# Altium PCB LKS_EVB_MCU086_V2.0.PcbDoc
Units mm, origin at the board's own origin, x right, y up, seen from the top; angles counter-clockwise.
Board outline 66.67 x 39.62 mm, 2 copper layers (Top Layer, Bottom Layer); 45 components, 69 nets, 205 pads, 49 vias.
Unrouted connection lines stored in the file: 4.
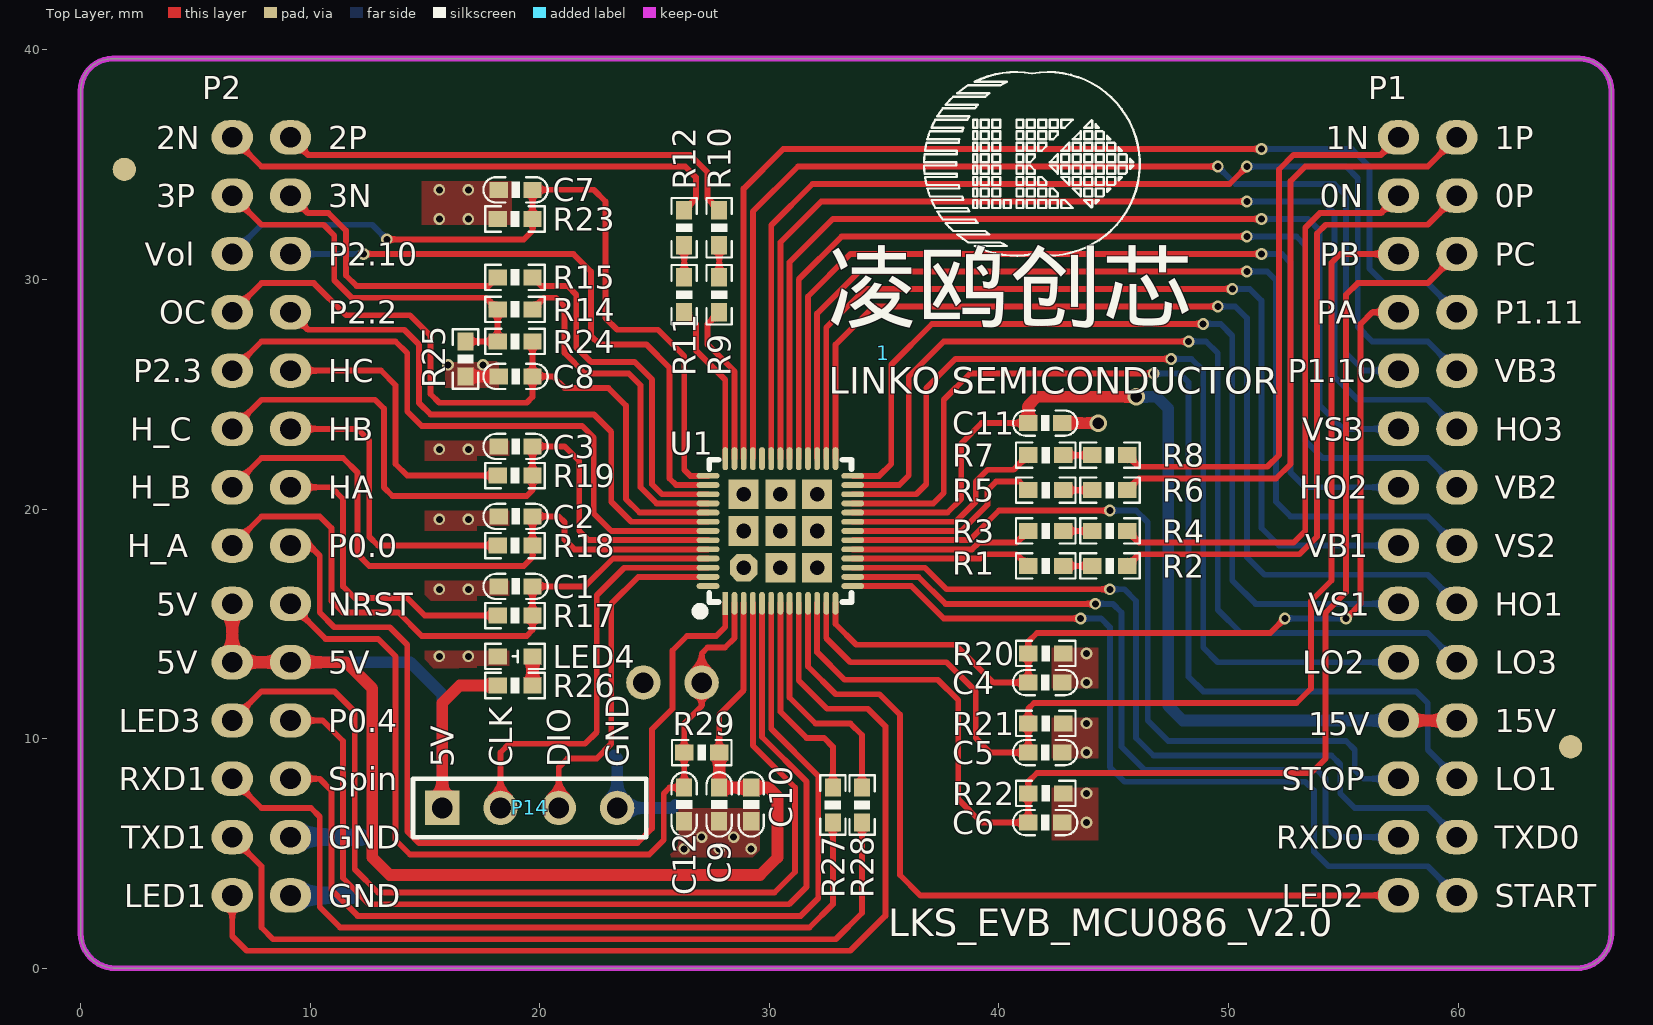
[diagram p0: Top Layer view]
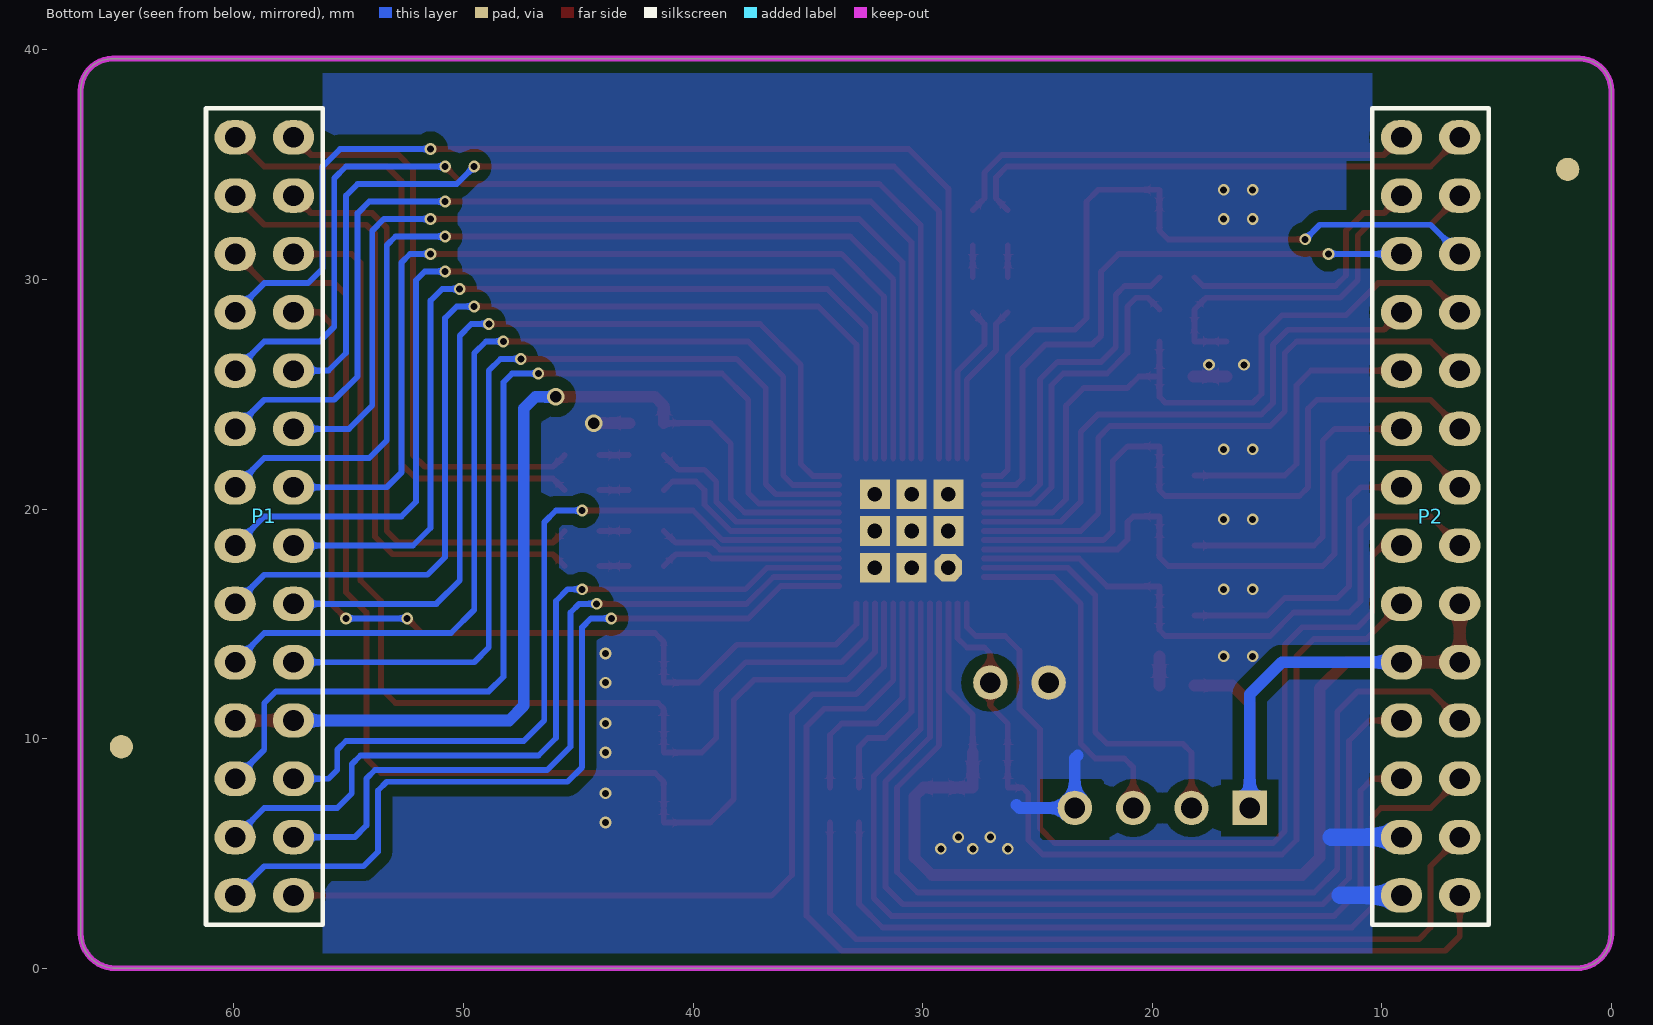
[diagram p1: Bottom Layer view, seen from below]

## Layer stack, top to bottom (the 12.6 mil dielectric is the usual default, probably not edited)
Top Solder: solder mask 0.0102, Solder Resist, Dk 3.5
Top Layer: signal copper 0.0356
Dielectric1: dielectric 0.32, FR-4, Dk 4.8
Bottom Layer: signal copper 0.0356
Bottom Solder: solder mask 0.0102, Solder Resist, Dk 3.5

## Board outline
0,1.524 0,38.227 cw(c1.397,38.227) 1.397,39.624 65.278,39.624 cw(c65.278,38.227) 66.675,38.227 66.675,1.524 cw(c65.151,1.524) 65.151,0 1.524,0 cw(c1.524,1.524)

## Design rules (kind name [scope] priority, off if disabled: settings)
Clearance Clearance_1 [InPolygon] p1: gap=0.508 ignorepadtopadclearanceinfootprint=FALSE except(0: Arc-Hole Track-Hole SMDPad-Hole THPad-Hole Via-Hole Fill-Hole Poly-Hole Region-Hole Text-Hole)
Clearance [All] p2: gap=0.076 ignorepadtopadclearanceinfootprint=FALSE except(0: Arc-Hole Track-Hole SMDPad-Hole THPad-Hole Via-Hole Fill-Hole Poly-Hole Region-Hole Text-Hole)
ComponentClearance [All] p1: gap=0 collisioncheckmode=3 verticalgap=0 showdistances=FALSE
FabricationTestpoint [(IsPad And (OnTopLayer Or OnBottomLayer))] p1: side=3 testpointundercomponent=TRUE minsize=1.016 maxsize=2.54 preferedsize=1.524 minholesize=0 maxholesize=1.016 preferedholesize=0.813 testpointgrid=0.025 allowsidetop=TRUE allowsidebottom=TRUE usegrid=TRUE gridtolerance=0
PolygonConnect [All] p1: connectstyle=Direct reliefconductorwidth=0.635 reliefentries=4 polygonreliefangle="90 Angle" airgapwidth=0.254
RoutingVias [All] p1: holewidth=0.711 width=1.27 viastyle="Through Hole" minholewidth=0 minwidth=0.254 maxholewidth=0.508 maxwidth=2.54
SilkToSolderMaskClearance SilkscreenOverComponentPads [IsPad] p1: minsilkscreentomaskgap=0.254 clearancetoexposedcopper=TRUE
SolderMaskExpansion [All] p1: expansion=0.102 istentingtop=FALSE
Width [All] p1: maxlimit=2.54 minlimit=0.051 preferedwidth=0.254
27 further rules are at their usual default settings.

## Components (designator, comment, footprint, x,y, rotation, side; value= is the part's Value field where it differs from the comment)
1 "LKS_sign" LKS_LOGO2 34.95,26.797 r0 top
C1 "10nF/16V" 0603C 18.948,16.637 r180 top
C2 "10nF/16V" 0603C 18.948,19.685 r180 top
C3 "10nF/16V" 0603C 18.948,22.733 r180 top
C4 "1nF/50V" 0603C 42.012,12.446 r0 top
C5 "1nF/50V" 0603C 42.012,9.398 r0 top
C6 "1nF/50V" 0603C 42.012,6.35 r0 top
C7 "100nF/50V" 0603C 18.947,33.909 r0 top
C8 "1nF/50V" 0603C 18.947,25.781 r0 top
C9 "10uF/16V" 0603C 27.813,7.136 r90 top
C10 "100nF/50V" 0603C 29.21,7.136 r90 top
C11 "4.7uF/35V" 0603C 42.013,23.749 r180 top
C12 "100nF/50V" 0603C 26.289,7.137 r270 top
LED4 "LED" "LED 0603R" 18.923,13.589 r0 top
P1 "Header 14X2A" "HDR 2X14 底层" 57.404,36.195 r180 bottom locked
P2 "Header 14X2A" "HDR 2X14 底层" 6.604,36.195 r180 bottom locked
P14 "Header 4" "HDR 1X4" 15.748,6.985 r0 top
R1 "20K1%" 0603R 42.037,17.526 r180 top value=K
R2 "20K1%" 0603R 44.831,17.526 r180 top value=K
R3 "20K1%" 0603R 42.037,19.05 r180 top value=K
R4 "20K1%" 0603R 44.831,19.05 r180 top value=K
R5 "20K1%" 0603R 42.037,20.828 r180 top value=K
R6 "20K1%" 0603R 44.831,20.828 r180 top value=K
R7 "20K1%" 0603R 42.037,22.352 r180 top value=K
R8 "20K1%" 0603R 44.831,22.352 r180 top value=K
R9 "20K1%" 0603R 27.813,29.337 r270 top value=K
R10 "20K1%" 0603R 27.813,32.258 r270 top value=K
R11 "20K1%" 0603R 26.289,29.337 r270 top value=K
R12 "20K1%" 0603R 26.289,32.258 r270 top value=K
R14 "1K1%" 0603R 18.923,28.702 r0 top value=K
R15 "1K1%" 0603R 18.923,30.099 r0 top value=K
R17 "2K" 0603R 18.923,15.367 r0 top value=K
R18 "2K" 0603R 18.923,18.415 r0 top value=K
R19 "2K" 0603R 18.923,21.463 r0 top value=K
R20 "1K" 0603R 42.037,13.716 r0 top value=K
R21 "1K" 0603R 42.037,10.668 r0 top value=K
R22 "1K" 0603R 42.037,7.62 r0 top value=K
R23 "1K1%" 0603R 18.923,32.639 r0 top value=K
R24 "1K1%" 0603R 18.923,27.305 r180 top value=K
R25 "10R" 0603R 16.764,26.543 r270 top value=10
R26 "330R" 0603R 18.923,12.319 r0 top value=330
R27 "10R" 0603R 32.766,7.112 r270 top
R28 "10R" 0603R 34.036,7.112 r90 top value=100R
R29 "20K" 0603R 27.051,9.398 r180 top value=K
U1 "LKS086" QFN52 30.48,19.05 r90 top locked

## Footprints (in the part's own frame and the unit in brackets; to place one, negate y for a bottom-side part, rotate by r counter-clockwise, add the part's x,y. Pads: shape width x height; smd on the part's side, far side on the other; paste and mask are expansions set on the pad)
0603C [mm] "电容"
  rect 0.8x0.7 smd: 1(-0.737,0) 2(0.738,0)
  silkscreen extent -1.4,-0.55 1.4,0.55, body extent -0.8,-0.41 0.8,0.41, height 0.81
0603R [mm] "电阻"
  rect 0.8x0.7 smd: 1(-0.762,0) 2(0.762,0)
  silkscreen extent -1.3,-0.55 1.3,0.55, body extent -0.8,-0.4 0.8,0.4, height 0.45
"HDR 1X4" [mm] "单排针 2.54mm"
  rect 1.5x1.5 hole 0.9: 1(0,0)
  round 1.5 hole 0.9: 2(2.54,0) 3(5.08,0) 4(7.62,0)
  silkscreen extent -1.27,-1.27 8.89,1.27, body extent -1.27,-1.27 8.89,1.27, height 8.5
"HDR 2X14 底层" [mm] "双排针 2.54mm 底层"
  oval 1.8x1.5 hole 0.9: 1(0,0) 2(0,-2.54) 3(0,-5.08) 4(0,-7.62) 5(0,-10.16) 6(0,-12.7) 7(0,-15.24) 8(0,-17.78) 9(0,-20.32) 10(0,-22.86) 11(0,-25.4) 12(0,-27.94) 13(0,-30.48) 14(0,-33.02) 15(-2.54,0) 16(-2.54,-2.54) 17(-2.54,-5.08) 18(-2.54,-7.62) 19(-2.54,-10.16) 20(-2.54,-12.7) 21(-2.54,-15.24) 22(-2.54,-17.78) 23(-2.54,-20.32) 24(-2.54,-22.86) 25(-2.54,-25.4) 26(-2.54,-27.94) 27(-2.54,-30.48) 28(-2.54,-33.02)
  silkscreen extent -3.81,-34.29 1.27,1.27, body extent -3.81,-34.29 1.27,1.27, height 8.5
"LED 0603R" [mm] "LED"
  rect 0.8x0.7 smd: 1(0.762,0) 2(-0.762,0)
  silkscreen extent -1.3,-0.55 1.3,0.55, body extent -0.8,-0.4 0.8,0.4, height 0.47
LKS_LOGO2 [mm] "标?"
  silkscreen extent 1.79,4.24 11.18,12.24
QFN52 [mm] "LINKO-086"
  oct 1.2x1.2 hole 0.635: 0(-1.6,1.6)
  rect 1.3x1.3 hole 0.635: 0(-1.6,0) 0(-1.6,-1.6) 0(0,1.6) 0(0,0) 0(0,-1.6) 0(1.6,1.6) 0(1.6,0) 0(1.6,-1.6)
  rect 1x0.25 smd: 1(-3.15,2.4)
  oval 1x0.25 smd: 2(-3.15,2) 3(-3.15,1.6) 4(-3.15,1.2) 5(-3.15,0.8) 6(-3.15,0.4) 7(-3.15,0) 8(-3.15,-0.4) 9(-3.15,-0.8) 10(-3.15,-1.2) 11(-3.15,-1.6) 12(-3.15,-2) 13(-3.15,-2.4) 27(3.15,-2.4) 28(3.15,-2) 29(3.15,-1.6) 30(3.15,-1.2) 31(3.15,-0.8) 32(3.15,-0.4) 33(3.15,0) 34(3.15,0.4) 35(3.15,0.8) 36(3.15,1.2) 37(3.15,1.6) 38(3.15,2) 39(3.15,2.4)
  oval 0.25x1 smd: 14(-2.4,-3.15) 15(-2,-3.15) 16(-1.6,-3.15) 17(-1.2,-3.15) 18(-0.8,-3.15) 19(-0.4,-3.15) 20(0,-3.15) 21(0.4,-3.15) 22(0.8,-3.15) 23(1.2,-3.15) 24(1.6,-3.15) 25(2,-3.15) 26(2.4,-3.15) 40(2.4,3.15) 41(2,3.15) 42(1.6,3.15) 43(1.2,3.15) 44(0.8,3.15) 45(0.4,3.15) 46(0,3.15) 47(-0.4,3.15) 48(-0.8,3.15) 49(-1.2,3.15) 50(-1.6,3.15) 51(-2,3.15) 52(-2.4,3.15)
  silkscreen extent -3.61,-3.1 3.1,3.61, body extent -3,-3 3,3, height 0.9

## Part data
C1 C2 C3 C4 C5 C6: library part CAP, "Capacitor"
C7 C8 C9 C10 C11 C12: library part C, "Capacitor"
LED4: "LED_Light"
P1 P2: "Header, 14-Pin, Dual row"
P14: "Header, 4-Pin"
R1 R2 R3 R4 R5 R6 R7 R8 R9 R10 R11 R12 R14 R15 R17 R18 R19 R20 R21 R22 R23 R24 R25 R26 R29: library part Res, "Resistor"
R27 R28: library part Res2, "Resistor"
U1: library part LKS086N8Q8, "芯片"

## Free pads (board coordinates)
  round 1.5 hole 0.9: 0(27.051,12.446) 1(24.511,12.446)
  round 1.016 all layers, no hole: 1(1.905,34.798) 2(64.897,9.652)

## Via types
v1: diameter 0.508, hole 0.305, Top Layer to Bottom Layer, 47 vias
v2: diameter 0.762, hole 0.508, Top Layer to Bottom Layer, 2 vias

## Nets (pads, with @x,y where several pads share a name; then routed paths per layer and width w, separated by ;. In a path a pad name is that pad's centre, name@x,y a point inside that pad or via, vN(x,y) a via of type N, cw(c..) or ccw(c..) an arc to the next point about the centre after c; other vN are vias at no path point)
+5V: C9.2 C10.2 P2.9 P2.10 P2.24 P14.1 R26.1 R29.1 U1.3 | length 68
  Top Layer w0.254: R29.1 27.813,11.049 28.88,12.116 U1.3
  Top Layer w0.508: P2.9 P2.10 P2.24 11.557,13.335 12.7,12.192 12.7,4.826 13.462,4.064 29.591,4.064 30.353,4.826 30.353,7.493 29.972,7.874 C10.2 C9.2 R29.1 ; P14.1 15.748,11.557 16.51,12.319 R26.1
  Bottom Layer w0.508: P2.24 14.351,13.335 15.748,11.938 P14.1
+15V: C11.2 P1.11 P1.25 U1.22 | length 43.7
  Top Layer w0.254: U1.22 37.757,19.85 38.354,20.447 38.354,22.86 39.243,23.749 C11.2
  Top Layer w0.508: C11.2 41.275,24.511 41.656,24.892 v2(45.974,24.892) ; P1.11 P1.25
  Bottom Layer w0.508: v2(45.974,24.892) 46.863,24.892 47.371,24.384 47.371,11.43 48.006,10.795 P1.11
GND: C1.2 C2.2 C3.2 C4.2 C5.2 C6.2 C7.1 C8.1 C9.1 C10.1 C11.1 C12.2 LED4.2 P2.16 P2.27 P2.28 P14.4 pad.1@24.511,12.446 R15.1 R20.2 R21.2 R22.2 R23.1 R25.2 U1.0 | length 25.6
  Top Layer w0.254: P2.16 9.906,32.893 10.795,32.893 11.557,32.131 11.557,30.182 12.021,29.718 17.78,29.718 R15.1
  Top Layer w0.508: R25.2 C8.1 ; C11.1 v2(44.323,23.749)
  Bottom Layer w0.508: 23.241,9.271 23.368,9.144 P14.4 25.781,6.985 25.908,7.112
  Bottom Layer w0.762: P2.28 11.811,3.175 ; P2.27 12.192,5.715
  other v1: 26.289,5.207 27.813,5.207 29.21,5.207 27.051,5.715 28.448,5.715 43.815,6.35 43.815,7.62 43.815,9.398 43.815,10.668 43.815,12.446 15.621,13.589 16.891,13.589 43.815,13.716 15.621,16.51 16.891,16.51 15.621,19.558 16.891,19.558 15.621,22.606 16.891,22.606 16.002,26.289 17.526,26.289 15.621,32.639 16.891,32.639 15.621,33.909 16.891,33.909
HALL_U: C1.1 P2.8 R17.2 U1.49 | length 27.8
  Top Layer w0.254: P2.8 7.874,19.685 10.414,19.685 10.922,19.177 10.922,16.002 11.43,15.494 13.843,15.494 14.859,14.478 19.431,14.478 19.685,14.732 R17.2 C1.1 21.971,16.637 23.184,17.85 U1.49
HALL_V: C2.1 P2.7 R18.2 U1.48 | length 28.3
  Top Layer w0.254: P2.7 7.874,22.225 11.43,22.225 12.065,21.59 12.065,18.034 12.573,17.526 19.304,17.526 19.685,17.907 R18.2 C2.1 20.828,19.685 21.082,19.431 21.082,18.669 21.501,18.25 U1.48
HALL_W: C3.1 P2.6 R19.2 U1.47 | length 30.5
  Top Layer w0.254: P2.6 7.874,24.765 12.827,24.765 13.208,24.384 13.208,20.955 13.589,20.574 19.431,20.574 19.685,20.828 R19.2 C3.1 21.082,22.733 21.717,22.098 21.717,19.05 22.117,18.65 U1.47
HO1: P1.23 U1.27 | length 44.2
  Top Layer w0.254: U1.27 32.88,27.165 34.544,28.829 v1(49.53,28.829)
  Bottom Layer w0.254: v1(49.53,28.829) 50.292,28.829 50.8,28.321 50.8,17.907 51.562,17.145 58.674,17.145 P1.23
HO2: P1.7 U1.30 | length 43.1
  Top Layer w0.254: U1.30 31.68,29.267 33.528,31.115 v1(51.435,31.115)
  Bottom Layer w0.254: v1(51.435,31.115) 52.324,31.115 52.705,30.734 52.705,21.59 53.34,20.955 P1.7
HO3: P1.20 U1.33 | length 47.9
  Top Layer w0.254: U1.33 30.48,31.623 32.258,33.401 v1(50.8,33.401)
  Bottom Layer w0.254: v1(50.8,33.401) 54.102,33.401 54.61,32.893 54.61,25.781 55.626,24.765 58.674,24.765 P1.20
HU: P2.21 R17.1 | length 13.6
  Top Layer w0.254: P2.21 10.922,20.955 11.43,20.447 11.43,16.637 11.938,16.129 14.224,16.129 14.986,15.367 R17.1
HV: P2.20 R18.1 | length 13.6
  Top Layer w0.254: P2.20 12.065,23.495 12.573,22.987 12.573,18.796 12.954,18.415 R18.1
HW: P2.19 R19.1 | length 12.9
  Top Layer w0.254: P2.19 13.081,26.035 13.716,25.4 13.716,21.971 14.224,21.463 R19.1
LED1: P2.14 U1.9 | length 47.3
  Top Layer w0.254: P2.14 6.604,1.397 7.239,0.762 33.528,0.762 35.052,2.286 35.052,10.541 34.29,11.303 32.512,11.303 31.28,12.535 U1.9
LED2: P1.14 U1.10 | length 36.7
  Top Layer w0.254: U1.10 31.68,13.151 32.893,11.938 34.798,11.938 35.687,11.049 35.687,4.064 36.576,3.175 P1.14
LED3: P2.11 U1.4 | length 45.5
  Top Layer w0.254: P2.11 7.874,12.065 11.049,12.065 11.938,11.176 11.938,4.318 12.954,3.302 30.226,3.302 31.115,4.191 31.115,7.874 29.28,9.709 U1.4
LO1: P1.26 U1.23 | length 47.1
  Top Layer w0.254: U1.23 37.141,20.25 37.592,20.701 37.592,24.765 38.735,25.908 v1(46.736,25.908)
  Bottom Layer w0.254: v1(46.736,25.908) 47.879,25.908 48.26,25.527 48.26,12.7 48.895,12.065 58.166,12.065 58.674,11.557 58.674,9.525 P1.26
LO2: P1.10 U1.24 | length 41.2
  Top Layer w0.254: U1.24 36.398,20.65 36.83,21.082 36.83,25.273 38.1,26.543 v1(47.498,26.543)
  Bottom Layer w0.254: v1(47.498,26.543) 48.387,26.543 48.895,26.035 48.895,13.97 49.53,13.335 P1.10
LO3: P1.24 U1.25 | length 43.8
  Top Layer w0.254: U1.25 35.655,21.05 36.068,21.463 36.068,25.781 37.592,27.305 v1(48.26,27.305)
  Bottom Layer w0.254: v1(48.26,27.305) 49.022,27.305 49.53,26.797 49.53,15.621 50.546,14.605 58.674,14.605 P1.24
NC: U1.35
NetLED4_1: LED4.1 R26.2 | length 1.3
  Top Layer w0.508: R26.2 LED4.1
NetR1_1: R1.1 R2.2 | length 1.3
  Top Layer w0.254: R1.1 R2.2
NetR3_1: R3.1 R4.2 | length 1.3
  Top Layer w0.254: R3.1 R4.2
NetR5_1: R5.1 R6.2 | length 1.3
  Top Layer w0.254: R5.1 R6.2
NetR7_1: R7.1 R8.2 | length 1.3
  Top Layer w0.254: R7.1 R8.2
NetR9_1: R9.1 R10.2 | length 1.4
  Top Layer w0.254: R9.1 R10.2
NetR11_1: R11.1 R12.2 | length 1.4
  Top Layer w0.254: R11.1 R12.2
NetR27_1: R27.1 U1.7 | length 9.4
  Top Layer w0.254: U1.7 30.48,11.176 31.623,10.033 32.385,10.033 32.766,9.652 R27.1
NetR28_2: R28.2 U1.8 | length 10.2
  Top Layer w0.254: U1.8 30.88,11.792 32.004,10.668 33.528,10.668 34.036,10.16 R28.2
NRST: C12.1 P2.23 pad.0 R29.2 U1.2 | length 38.1
  Top Layer w0.254: P2.23 10.668,14.351 12.954,14.351 13.716,13.589 13.716,5.588 14.351,4.953 24.765,4.953 25.4,5.588 25.4,7.62 25.654,7.874 C12.1 R29.2 26.289,10.668 27.051,11.43 pad.0 27.051,13.716 27.305,13.97 28.067,13.97 28.48,14.383 U1.2
OC: C8.2 P2.4 R24.1 U1.44 | length 32.3
  Top Layer w0.254: P2.4 7.874,29.845 10.16,29.845 11.557,28.448 14.351,28.448 15.24,27.559 15.24,25.019 15.621,24.638 19.431,24.638 19.685,24.892 C8.2 ; R24.1 C8.2 ; U1.44 24.346,19.85 23.749,20.447 23.749,24.511 22.987,25.273 21.082,25.273 20.574,25.781 C8.2
OPA0_IN: R3.2 U1.18 | length 8
  Top Layer w0.254: U1.18 37.503,18.25 38.824,18.25 39.116,18.542 40.767,18.542 R3.2
OPA0_IP: R1.2 U1.17 | length 7.9
  Top Layer w0.254: U1.17 37.141,17.85 39.186,17.85 39.37,18.034 40.767,18.034 R1.2
OPA1_IN: R7.2 U1.21 | length 9.4
  Top Layer w0.254: U1.21 38.119,19.45 38.989,20.32 38.989,21.209 39.497,21.717 40.64,21.717 R7.2
OPA1_IP: R5.2 U1.20 | length 9.1
  Top Layer w0.254: U1.20 38.354,19.05 39.497,20.193 39.497,20.828 39.878,21.209 40.894,21.209 R5.2
OPA2_IN: R11.2 U1.39 | length 7.1
  Top Layer w0.254: R11.2 26.797,28.067 26.797,26.924 28.08,25.641 U1.39
OPA2_IP: R9.2 U1.38 | length 7.1
  Top Layer w0.254: R9.2 27.305,28.067 27.305,27.178 28.48,26.003 U1.38
OPA3_IN: R15.2 U1.42 | length 15.6
  Top Layer w0.254: R15.2 20.066,29.718 21.209,29.718 21.59,29.337 21.59,27.051 22.225,26.416 24.13,26.416 24.892,25.654 24.892,21.082 25.324,20.65 U1.42
OPA3_IP: R14.2 U1.43 | length 15.4
  Top Layer w0.254: R14.2 20.193,29.21 20.701,29.21 21.082,28.829 21.082,26.797 21.971,25.908 23.876,25.908 24.384,25.4 24.384,20.955 25.089,20.25 U1.43
P0.0: P2.22 U1.1 | length 39.5
  Top Layer w0.254: P2.22 9.97,18.415 10.414,17.97 10.414,15.494 11.049,14.859 13.462,14.859 14.224,14.097 14.224,5.969 14.732,5.461 24.257,5.461 24.892,6.096 24.892,10.414 25.781,11.303 25.781,13.843 26.416,14.478 27.686,14.478 28.08,14.872 U1.1
P0.4: P2.25 U1.5 | length 42.8
  Top Layer w0.254: P2.25 10.541,10.795 11.43,9.906 11.43,3.937 12.573,2.794 30.861,2.794 31.623,3.556 31.623,8.128 29.68,10.071 U1.5
P1.10: P1.5 U1.36 | length 47.4
  Top Layer w0.254: U1.36 29.28,32.963 31.242,34.925 v1(49.53,34.925)
  Bottom Layer w0.254: v1(49.53,34.925) 50.292,34.163 54.61,34.163 55.118,33.655 55.118,26.797 55.88,26.035 P1.5
P1.11: P1.18 U1.37 | length 49.1
  Top Layer w0.254: U1.37 28.88,33.96 30.607,35.687 v1(51.434,35.687)
  Bottom Layer w0.254: v1(51.434,35.687) 55.372,35.687 56.134,34.925 56.134,30.48 56.769,29.845 58.674,29.845 P1.18
P2.2: P2.18 U1.45 | length 25.2
  Top Layer w0.254: P2.18 9.906,27.813 14.097,27.813 14.732,27.178 14.732,24.638 15.24,24.13 22.352,24.13 23.114,23.368 23.114,20.32 23.984,19.45 U1.45
P2.3: P2.5 U1.46 | length 28.1
  Top Layer w0.254: P2.5 7.874,27.305 13.716,27.305 14.224,26.797 14.224,24.257 14.859,23.622 21.844,23.622 22.352,23.114 22.352,19.812 23.114,19.05 U1.46
P2.10: P2.17 U1.41 | length 26.8
  Top Layer w0.254: v1(12.319,31.115) 21.463,31.115 22.225,30.353 22.225,27.559 22.606,27.178 24.638,27.178 25.654,26.162 25.654,21.336 25.94,21.05 U1.41
  Bottom Layer w0.254: P2.17 v1(12.319,31.115)
P2.15: U1.52
PGND: P1.1 P1.2 P2.1 P2.2 R4.1 R8.1 R12.1 R14.1 R24.2 R25.1 | length 91.4
  Top Layer w0.254: P2.2 7.874,32.385 10.585,32.385 11.049,31.921 11.049,29.972 11.811,29.21 17.653,29.21 R14.1 R24.2 R25.1 ; P2.1 7.874,34.925 26.333,34.925 26.797,34.461 26.797,33.528 R12.1 ; R4.1 46.101,18.542 52.832,18.542 53.34,19.05 53.34,32.258 53.975,32.893 56.642,32.893 P1.2 ; R8.1 46.101,21.844 51.689,21.844 52.197,22.352 52.197,34.798 52.832,35.433 56.642,35.433 P1.1
PU: C4.1 P1.4 R20.1 U1.13 | length 41.3
  Top Layer w0.254: U1.13 32.88,14.999 33.782,14.097 38.1,14.097 39.751,12.446 C4.1 R20.1 41.275,14.224 41.656,14.605 51.816,14.605 v1(52.451,15.24) ; v1(55.118,15.24) 55.753,15.875 55.753,28.067 56.261,28.575 P1.4
  Bottom Layer w0.254: v1(52.451,15.24) v1(55.118,15.24)
PV: C5.1 P1.3 R21.1 U1.12 | length 50.1
  Top Layer w0.254: U1.12 32.48,14.383 33.528,13.335 37.719,13.335 38.989,12.065 38.989,10.033 39.624,9.398 C5.1 R21.1 41.275,11.303 41.529,11.557 52.959,11.557 53.594,12.192 53.594,16.002 54.483,16.891 54.483,30.734 54.864,31.115 P1.3
PW: C6.1 P1.17 R22.1 U1.11 | length 58.2
  Top Layer w0.254: U1.11 32.08,13.767 33.274,12.573 37.338,12.573 38.227,11.684 38.227,7.366 39.243,6.35 C6.1 R22.1 41.275,8.128 41.656,8.509 53.594,8.509 54.229,9.144 54.229,15.494 55.118,16.383 55.118,29.337 55.626,29.845 58.674,29.845 P1.17
RXD0: P1.13 U1.15 | length 33.1
  Top Layer w0.254: U1.15 36.493,17.05 37.668,15.875 v1(44.196,15.875)
  Bottom Layer w0.254: v1(44.196,15.875) 44.958,15.875 45.339,15.494 45.339,9.652 46.355,8.636 53.848,8.636 54.229,8.255 54.229,6.223 54.737,5.715 P1.13
RXD1: P2.12 R27.2 | length 35.1
  Top Layer w0.254: P2.12 7.874,6.985 10.033,6.985 10.414,6.604 10.414,2.667 11.303,1.778 31.75,1.778 32.766,2.794 R27.2
SPIN: P2.26 U1.6 | length 42
  Top Layer w0.254: P2.26 10.414,8.255 10.922,7.747 10.922,3.429 12.065,2.286 31.369,2.286 32.131,3.048 32.131,8.382 30.08,10.433 U1.6
START1: P1.28 U1.14 | length 37
  Top Layer w0.254: U1.14 36.182,16.65 37.592,15.24 v1(43.561,15.24)
  Bottom Layer w0.254: v1(43.561,15.24) 44.45,15.24 44.831,14.859 44.831,8.763 45.466,8.128 53.34,8.128 53.721,7.747 53.721,5.08 54.356,4.445 58.674,4.445 P1.28
STOP1: P1.12 U1.19 | length 34.7
  Top Layer w0.254: U1.19 38.716,18.65 40.005,19.939 v1(44.831,19.939)
  Bottom Layer w0.254: v1(44.831,19.939) 45.974,19.939 46.482,19.431 46.482,10.795 47.371,9.906 55.118,9.906 55.499,9.525 55.499,8.636 55.88,8.255 P1.12
SWCLK: P14.2 U1.50 | length 18.3
  Top Layer w0.254: P14.2 18.288,9.398 18.669,9.779 21.971,9.779 22.479,10.287 22.479,16.256 23.673,17.45 U1.50
SWDIO: P14.3 U1.51 | length 15.3
  Top Layer w0.254: P14.3 20.828,8.763 21.209,9.144 22.479,9.144 23.114,9.779 23.114,15.875 24.289,17.05 U1.51
TXD0: P1.27 U1.16 | length 35.4
  Top Layer w0.254: U1.16 36.779,17.45 37.719,16.51 v1(44.831,16.51)
  Bottom Layer w0.254: v1(44.831,16.51) 45.466,16.51 45.974,16.002 45.974,10.033 46.736,9.271 54.483,9.271 54.864,8.89 54.864,7.62 55.499,6.985 58.674,6.985 P1.27
TXD1: P2.13 R28.1 | length 35.2
  Top Layer w0.254: P2.13 7.874,4.445 7.874,1.778 8.382,1.27 32.893,1.27 34.036,2.413 R28.1
UP-: P2.15 R10.1 | length 20.7
  Top Layer w0.254: P2.15 9.906,35.433 26.543,35.433 27.305,34.671 27.305,33.528 R10.1
VB1: P1.8 U1.28 | length 41.8
  Top Layer w0.254: U1.28 32.48,27.908 34.163,29.591 v1(50.165,29.591)
  Bottom Layer w0.254: v1(50.165,29.591) 50.927,29.591 51.435,29.083 51.435,19.177 52.197,18.415 P1.8
VB2: P1.21 U1.31 | length 46.8
  Top Layer w0.254: U1.31 31.28,30.01 33.147,31.877 v1(50.8,31.877)
  Bottom Layer w0.254: v1(50.8,31.877) 52.959,31.877 53.34,31.496 53.34,22.987 54.102,22.225 58.674,22.225 P1.21
VB3: P1.19 U1.34 | length 48.6
  Top Layer w0.254: U1.34 30.08,32.366 31.877,34.163 50.038,34.163 v1(50.8,34.925)
  Bottom Layer w0.254: v1(50.8,34.925) 55.118,34.925 55.626,34.417 55.626,27.94 56.261,27.305 58.674,27.305 P1.19
VOL_ADC: C7.2 P2.3 R23.2 U1.40 | length 34.5
  Top Layer w0.254: v1(13.335,31.75) 19.304,31.75 19.685,32.131 R23.2 C7.2 22.352,33.909 22.86,33.401 22.86,28.321 23.368,27.813 25.146,27.813 26.289,26.67 26.289,21.717 26.556,21.45 U1.40
  Bottom Layer w0.254: P2.3 7.874,32.385 12.7,32.385 v1(13.335,31.75)
VP-: P1.15 R6.1 | length 27.9
  Top Layer w0.254: R6.1 46.101,21.336 52.07,21.336 52.705,21.971 52.705,34.29 53.34,34.925 58.674,34.925 P1.15
VS1: P1.9 U1.26 | length 40.3
  Top Layer w0.254: U1.26 34.785,21.45 35.306,21.971 35.306,26.289 37.084,28.067 v1(48.895,28.067)
  Bottom Layer w0.254: v1(48.895,28.067) 49.657,28.067 50.165,27.559 50.165,16.891 51.181,15.875 P1.9
VS2: P1.22 U1.29 | length 45.5
  Top Layer w0.254: U1.29 32.08,28.524 33.909,30.353 v1(50.8,30.353)
  Bottom Layer w0.254: v1(50.8,30.353) 51.689,30.353 52.07,29.972 52.07,20.32 52.705,19.685 58.674,19.685 P1.22
VS3: P1.6 U1.32 | length 44.1
  Top Layer w0.254: U1.32 30.88,30.753 32.766,32.639 v1(51.435,32.639)
  Bottom Layer w0.254: v1(51.435,32.639) 53.467,32.639 53.975,32.131 53.975,24.511 54.991,23.495 P1.6
WP-: P1.16 R2.1 | length 28.8
  Top Layer w0.254: R2.1 46.101,18.034 53.086,18.034 53.848,18.796 53.848,32.004 54.229,32.385 58.674,32.385 P1.16

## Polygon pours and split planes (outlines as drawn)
GND on Top Layer "NONET_L-01_P-001" (solid, remove dead copper, pour order 13): 18.669,13.081 15.367,13.081 14.986,13.462 14.986,23.241 15.494,23.749 18.669,23.749
GND on Top Layer "NONET_L-01_P-001" (solid, remove dead copper, pour order 15): 18.796,34.925 18.796,32.004 18.542,31.75 15.367,31.75 14.859,32.258 14.859,34.417 15.367,34.925
GND on Top Layer "NONET_L-01_P-001" (solid, remove dead copper, pour order 14): 15.621,26.797 17.78,26.797 18.21,26.367 18.21,25.068 17.907,24.765 15.748,24.765 15.621,24.892
GND on Top Layer "NONET_L-01_P-001" (solid, remove dead copper, pour order 12): 42.291,14.605 42.291,5.588 44.323,5.588 44.323,14.605
GND on Top Layer "NONET_L-01_P-001" (solid, remove dead copper, pour order 11): 25.654,7.112 30.353,7.112 30.353,4.826 29.591,4.064 25.654,4.064
GND on Bottom Layer "Bottom Layer-No Net 1" (solid, remove dead copper, pour order 10): 10.414,39.624 10.414,0 56.134,0 56.134,39.624

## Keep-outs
Keep-Out Layer:
  the board outline again, w0.254

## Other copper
Bottom Layer:
  pour cut-out: 22.098,8.128 22.225,8.255 24.892,8.255 24.892,5.715 24.765,5.588 21.844,5.588
  pour cut-out: 8.001,35.052 8.128,35.179 11.557,35.179 11.557,32.258 11.303,32.004 8.128,32.004

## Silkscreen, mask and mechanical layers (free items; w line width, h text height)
Top Overlay:
  text "2N" at 3.302,35.687 h1
  text "2P" at 10.795,35.687 h1
  text "1N" at 54.229,35.687 h1
  text "1P" at 61.595,35.687 h1
  text "3P" at 3.302,33.147 h1
  text "3N" at 10.795,33.147 h1
  text "0N" at 53.975,33.147 h1
  text "0P" at 61.595,33.147 h1
  text "Vol" at 2.794,30.607 h1
  text "P2.10" at 10.795,30.607 h1
  text "PB" at 53.975,30.607 h1
  text "PC" at 61.595,30.607 h1
  text "OC" at 3.429,28.067 h1
  text "P2.2" at 10.795,28.067 h1
  text "PA" at 53.848,28.067 h1
  text "P1.11" at 61.595,28.067 h1
  text "P2.3" at 2.286,25.527 h1
  text "HC" at 10.795,25.527 h1
  text "P1.10" at 52.578,25.527 h1
  text "VB3" at 61.595,25.527 h1
  text "H_C" at 2.159,22.987 h1
  text "HB" at 10.795,22.987 h1
  text "VS3" at 53.213,22.987 h1
  text "HO3" at 61.595,22.987 h1
  text "H_B" at 2.159,20.447 h1
  text "HA" at 10.795,20.447 h1
  text "HO2" at 53.086,20.447 h1
  text "VB2" at 61.595,20.447 h1
  text "H_A" at 2.032,17.907 h1
  text "P0.0" at 10.795,17.907 h1
  text "VB1" at 53.34,17.907 h1
  text "VS2" at 61.595,17.907 h1
  text "5V" at 3.302,15.367 h1
  text "NRST" at 10.795,15.367 h1
  text "VS1" at 53.467,15.367 h1
  text "HO1" at 61.595,15.367 h1
  text "5V" at 3.302,12.827 h1
  text "5V" at 10.795,12.827 h1
  text "LO2" at 53.213,12.827 h1
  text "LO3" at 61.595,12.827 h1
  text "LED3" at 1.651,10.287 h1
  text "P0.4" at 10.795,10.287 h1
  text "15V" at 61.595,10.287 h1
  text "15V" at 53.467,10.16 h1
  text "5V" at 16.256,8.763 h1 r90
  text "CLK" at 18.796,8.763 h1 r90
  text "DIO" at 21.336,8.763 h1 r90
  text "GND" at 23.876,8.763 h1 r90
  text "RXD1" at 1.651,7.747 h1
  text "Spin" at 10.795,7.747 h1
  text "STOP" at 52.324,7.747 h1
  text "LO1" at 61.595,7.747 h1
  text "TXD1" at 1.778,5.207 h1
  text "GND" at 10.795,5.207 h1
  text "RXD0" at 52.07,5.207 h1
  text "TXD0" at 61.595,5.207 h1
  text "LED1" at 1.905,2.667 h1
  text "GND" at 10.795,2.667 h1
  text "LED2" at 52.324,2.667 h1
  text "START" at 61.595,2.667 h1
  text "LKS_EVB_MCU086_V2.0" at 35.179,1.016 h2.03
Top Solder:
  circle w1.981: c64.897,9.652 r0.432
  circle w1.981: c1.905,34.798 r0.432
Mechanical 1:
  the board outline again, w0.254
